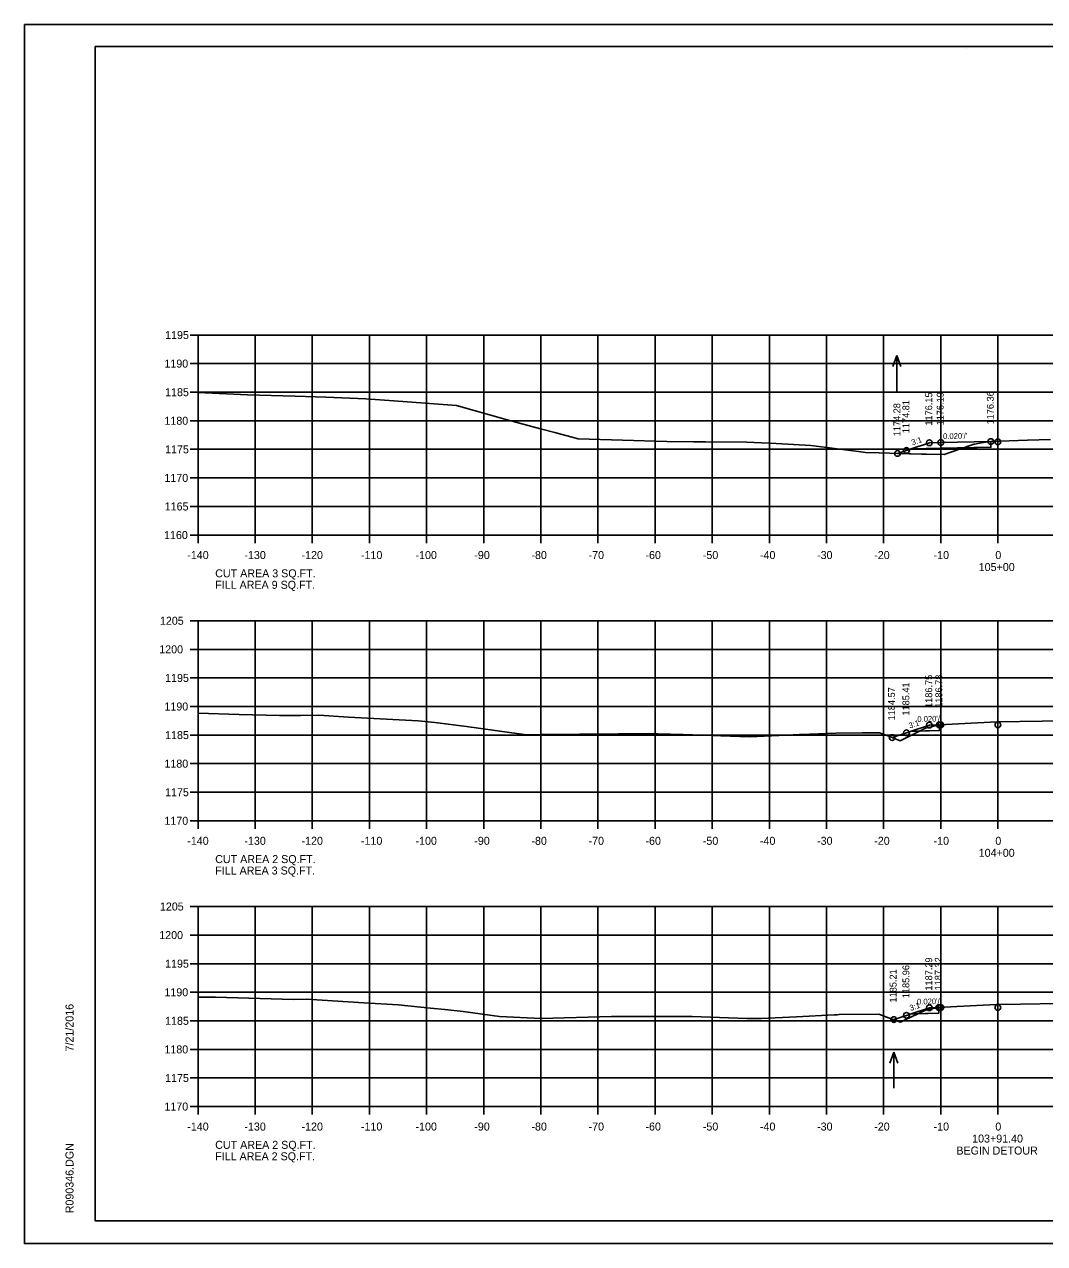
# Model space of a CAD drawing. Extents: x 1368971 to 1374497, y 378717 to 381839.
# Drawn here: x 1372238.5 to 1372417.1, y 380690 to 380903.3 of the extents above; entities that cross this region are included whole.
import ezdxf

# ---------------------------------------------------------------- set-up
doc = ezdxf.new("R2010")
doc.units = 0
for name, color, linetype in [('R_Alt Surface', 7, 'Continuous'), ('R_Axis', 7, 'Continuous'), ('R_Axis Annot', 7, 'Continuous'), ('R_Border', 7, 'Continuous'), ('R_Contours', 7, 'Continuous'), ('R_Exist Surface', 7, 'Continuous'), ('R_Fin Surface', 7, 'Continuous'), ('R_Grid', 7, 'Continuous'), ('R_No Plot', 7, 'Continuous'), ('R_Water Annot', 7, 'Continuous'), ('R_Xsect Elev', 7, 'Continuous'), ('R_Xsect Slope', 7, 'Continuous')]:
    doc.layers.add(name, color=color, linetype=linetype)

msp = doc.modelspace()

# ---------------------------------------------------------------- linework, layer by layer
at = {"layer": 'R_Alt Surface'}
for points in [[(1372407.68, 380830.34), (1372407.68, 380829.34), (1372398.91, 380829.17), (1372393.72, 380829.06)], [(1372398.66, 380780.76), (1372398.66, 380779.76), (1372393.72, 380779.66)], [(1372398.57, 380731.3), (1372398.57, 380730.3), (1372393.72, 380730.21)]]:
    msp.add_lwpolyline(points, dxfattribs=at)
at = {"layer": 'R_Axis'}
for p, q in [((1372267.51, 380848.98), (1372268.91, 380848.98)), ((1372268.91, 380813.98), (1372268.91, 380848.98)), ((1372267.51, 380843.98), (1372268.91, 380843.98)), ((1372267.51, 380838.98), (1372268.91, 380838.98)), ((1372267.51, 380833.98), (1372268.91, 380833.98)), ((1372267.51, 380828.98), (1372268.91, 380828.98)), ((1372267.51, 380823.98), (1372268.91, 380823.98)), ((1372267.51, 380818.98), (1372268.91, 380818.98)), ((1372267.51, 380813.98), (1372268.91, 380813.98)), ((1372268.91, 380813.98), (1372548.91, 380813.98)), ((1372268.91, 380812.58), (1372268.91, 380813.98)), ((1372278.91, 380812.58), (1372278.91, 380813.98)), ((1372288.91, 380812.58), (1372288.91, 380813.98)), ((1372298.91, 380812.58), (1372298.91, 380813.98)), ((1372308.91, 380812.58), (1372308.91, 380813.98)), ((1372318.91, 380812.58), (1372318.91, 380813.98)), ((1372328.91, 380812.58), (1372328.91, 380813.98)), ((1372338.91, 380812.58), (1372338.91, 380813.98)), ((1372348.91, 380812.58), (1372348.91, 380813.98)), ((1372358.91, 380812.58), (1372358.91, 380813.98)), ((1372368.91, 380812.58), (1372368.91, 380813.98)), ((1372378.91, 380812.58), (1372378.91, 380813.98)), ((1372388.91, 380812.58), (1372388.91, 380813.98)), ((1372398.91, 380812.58), (1372398.91, 380813.98)), ((1372408.91, 380812.58), (1372408.91, 380813.98)), ((1372267.51, 380798.98), (1372268.91, 380798.98)), ((1372268.91, 380763.98), (1372268.91, 380798.98)), ((1372267.51, 380793.98), (1372268.91, 380793.98)), ((1372267.51, 380788.98), (1372268.91, 380788.98)), ((1372267.51, 380783.98), (1372268.91, 380783.98)), ((1372267.51, 380778.98), (1372268.91, 380778.98)), ((1372267.51, 380773.98), (1372268.91, 380773.98)), ((1372267.51, 380768.98), (1372268.91, 380768.98)), ((1372267.51, 380763.98), (1372268.91, 380763.98)), ((1372268.91, 380763.98), (1372548.91, 380763.98)), ((1372268.91, 380762.58), (1372268.91, 380763.98)), ((1372278.91, 380762.58), (1372278.91, 380763.98)), ((1372288.91, 380762.58), (1372288.91, 380763.98)), ((1372298.91, 380762.58), (1372298.91, 380763.98)), ((1372308.91, 380762.58), (1372308.91, 380763.98)), ((1372318.91, 380762.58), (1372318.91, 380763.98)), ((1372328.91, 380762.58), (1372328.91, 380763.98)), ((1372338.91, 380762.58), (1372338.91, 380763.98)), ((1372348.91, 380762.58), (1372348.91, 380763.98)), ((1372358.91, 380762.58), (1372358.91, 380763.98)), ((1372368.91, 380762.58), (1372368.91, 380763.98)), ((1372378.91, 380762.58), (1372378.91, 380763.98)), ((1372388.91, 380762.58), (1372388.91, 380763.98)), ((1372398.91, 380762.58), (1372398.91, 380763.98)), ((1372408.91, 380762.58), (1372408.91, 380763.98)), ((1372267.51, 380748.98), (1372268.91, 380748.98)), ((1372268.91, 380713.98), (1372268.91, 380748.98)), ((1372267.51, 380743.98), (1372268.91, 380743.98)), ((1372267.51, 380738.98), (1372268.91, 380738.98)), ((1372267.51, 380733.98), (1372268.91, 380733.98)), ((1372267.51, 380728.98), (1372268.91, 380728.98)), ((1372267.51, 380723.98), (1372268.91, 380723.98)), ((1372267.51, 380718.98), (1372268.91, 380718.98)), ((1372267.51, 380713.98), (1372268.91, 380713.98)), ((1372268.91, 380713.98), (1372548.91, 380713.98)), ((1372268.91, 380712.58), (1372268.91, 380713.98)), ((1372278.91, 380712.58), (1372278.91, 380713.98)), ((1372288.91, 380712.58), (1372288.91, 380713.98)), ((1372298.91, 380712.58), (1372298.91, 380713.98)), ((1372308.91, 380712.58), (1372308.91, 380713.98)), ((1372318.91, 380712.58), (1372318.91, 380713.98)), ((1372328.91, 380712.58), (1372328.91, 380713.98)), ((1372338.91, 380712.58), (1372338.91, 380713.98)), ((1372348.91, 380712.58), (1372348.91, 380713.98)), ((1372358.91, 380712.58), (1372358.91, 380713.98)), ((1372368.91, 380712.58), (1372368.91, 380713.98)), ((1372378.91, 380712.58), (1372378.91, 380713.98)), ((1372388.91, 380712.58), (1372388.91, 380713.98)), ((1372398.91, 380712.58), (1372398.91, 380713.98)), ((1372408.91, 380712.58), (1372408.91, 380713.98))]:
    msp.add_line(p, q, dxfattribs=at)
at = {"layer": 'R_Border'}
for p, q in [((1372250.91, 380899.44), (1372567.09, 380899.44)), ((1372250.91, 380693.98), (1372250.91, 380899.44)), ((1372403.43, 380899.18), (1372403.43, 380899.18)), ((1372403.43, 380899.18), (1372403.43, 380899.18)), ((1372250.91, 380693.98), (1372250.91, 380693.98)), ((1372567.09, 380693.98), (1372250.91, 380693.98))]:
    msp.add_line(p, q, dxfattribs=at)
at = {"layer": 'R_Contours'}
for points in [[(1372391.33, 380828.26), (1372395.51, 380828.16), (1372396.42, 380828.12), (1372399.49, 380828.06), (1372402, 380828.96), (1372402.87, 380829.25), (1372398.91, 380829.17), (1372393.72, 380829.06), (1372392.91, 380828.79)], [(1372402.87, 380829.25), (1372404.77, 380829.87), (1372406.37, 380830.15), (1372407.68, 380830.34), (1372407.68, 380829.34)], [(1372395.23, 380779.69), (1372396.23, 380780.17), (1372397.02, 380780.35), (1372398.66, 380780.76), (1372398.66, 380779.76)], [(1372390.39, 380778.55), (1372391.8, 380777.99), (1372395.17, 380779.67), (1372395.23, 380779.69), (1372393.72, 380779.66), (1372392.91, 380779.39)], [(1372394.92, 380730.23), (1372396.11, 380730.8), (1372397.61, 380731.13), (1372398.57, 380731.3), (1372398.57, 380730.3)], [(1372390.67, 380729.19), (1372391.85, 380728.76), (1372392.69, 380729.15), (1372394.92, 380730.23), (1372393.72, 380730.21), (1372392.91, 380729.94)]]:
    msp.add_lwpolyline(points, close=True, dxfattribs=at)
at = {"layer": 'R_Exist Surface'}
for points in [[(1372268.91, 380838.94), (1372277.57, 380838.53), (1372285.93, 380838.26), (1372291.29, 380838.13), (1372298.29, 380837.83), (1372303.19, 380837.45), (1372314.16, 380836.66), (1372322.99, 380834.15), (1372328.85, 380832.55), (1372331.35, 380831.93), (1372335.44, 380830.84), (1372350.98, 380830.33), (1372355.63, 380830.27), (1372357.71, 380830.28), (1372364.97, 380830.22), (1372370.07, 380829.99), (1372376.18, 380829.62), (1372384.51, 380828.59), (1372385.73, 380828.42), (1372388.15, 380828.35), (1372395.51, 380828.16), (1372396.42, 380828.12), (1372399.49, 380828.06), (1372402, 380828.96), (1372404.77, 380829.87), (1372406.37, 380830.15), (1372407.68, 380830.34), (1372414.1, 380830.59), (1372418.1, 380830.72)], [(1372268.91, 380782.81), (1372276.11, 380782.6), (1372283.18, 380782.38), (1372286.83, 380782.39), (1372290.04, 380782.44), (1372295.23, 380782.09), (1372307.43, 380781.5), (1372310.37, 380781.19), (1372315.87, 380780.5), (1372323.43, 380779.44), (1372325.96, 380779.08), (1372327.07, 380779.02), (1372328.92, 380779.08), (1372342.51, 380779.17), (1372349.38, 380779.18), (1372353.8, 380779.1), (1372363.72, 380778.72), (1372365.48, 380778.66), (1372373.08, 380779.03), (1372374.16, 380779.08), (1372374.44, 380779.09), (1372380.54, 380779.31), (1372385.13, 380779.35), (1372388.17, 380779.39), (1372389.98, 380778.71), (1372391.8, 380777.99), (1372395.17, 380779.67), (1372396.23, 380780.17), (1372397.02, 380780.35), (1372398.66, 380780.76), (1372405.35, 380781.12), (1372408.81, 380781.3), (1372416.67, 380781.41), (1372419.84, 380781.45)], [(1372268.91, 380733.14), (1372271.97, 380733.1), (1372281.73, 380732.82), (1372285.53, 380732.73), (1372287.87, 380732.78), (1372297.92, 380732.1), (1372303.92, 380731.8), (1372309.57, 380731.22), (1372312.09, 380730.96), (1372315.32, 380730.64), (1372321.7, 380729.75), (1372328.96, 380729.38), (1372341.29, 380729.76), (1372341.37, 380729.76), (1372341.52, 380729.76), (1372352.86, 380729.73), (1372355.4, 380729.74), (1372364.97, 380729.39), (1372367.5, 380729.41), (1372373.66, 380729.67), (1372380.23, 380730.03), (1372380.75, 380730.05), (1372381.14, 380730.06), (1372388.08, 380730.15), (1372390.23, 380729.35), (1372391.85, 380728.76), (1372392.69, 380729.15), (1372396.11, 380730.8), (1372397.61, 380731.13), (1372398.57, 380731.3), (1372401.75, 380731.48), (1372408.68, 380731.86), (1372412.88, 380731.92), (1372419.7, 380732.02)]]:
    msp.add_lwpolyline(points, dxfattribs=at)
at = {"layer": 'R_Fin Surface'}
for points in [[(1372391.33, 380828.26), (1372392.91, 380828.79), (1372393.72, 380829.06), (1372396.91, 380830.13), (1372398.91, 380830.17), (1372407.68, 380830.34)], [(1372390.39, 380778.55), (1372392.91, 380779.39), (1372393.72, 380779.66), (1372396.91, 380780.73), (1372398.66, 380780.76), (1372398.91, 380780.77)], [(1372390.67, 380729.19), (1372392.91, 380729.94), (1372393.72, 380730.21), (1372396.91, 380731.27), (1372398.57, 380731.3), (1372398.91, 380731.31)]]:
    msp.add_lwpolyline(points, dxfattribs=at)
at = {"layer": 'R_Grid'}
for p, q in [((1372268.91, 380848.98), (1372548.91, 380848.98)), ((1372268.91, 380813.98), (1372268.91, 380848.98)), ((1372278.91, 380813.98), (1372278.91, 380848.98)), ((1372288.91, 380813.98), (1372288.91, 380848.98)), ((1372298.91, 380813.98), (1372298.91, 380848.98)), ((1372308.91, 380813.98), (1372308.91, 380848.98)), ((1372318.91, 380813.98), (1372318.91, 380848.98)), ((1372328.91, 380813.98), (1372328.91, 380848.98)), ((1372338.91, 380813.98), (1372338.91, 380848.98)), ((1372348.91, 380813.98), (1372348.91, 380848.98)), ((1372358.91, 380813.98), (1372358.91, 380848.98)), ((1372368.91, 380813.98), (1372368.91, 380848.98)), ((1372378.91, 380813.98), (1372378.91, 380848.98)), ((1372388.91, 380813.98), (1372388.91, 380848.98)), ((1372398.91, 380813.98), (1372398.91, 380848.98)), ((1372408.91, 380813.98), (1372408.91, 380848.98)), ((1372268.91, 380843.98), (1372548.91, 380843.98)), ((1372268.91, 380838.98), (1372548.91, 380838.98)), ((1372268.91, 380833.98), (1372548.91, 380833.98)), ((1372268.91, 380828.98), (1372548.91, 380828.98)), ((1372268.91, 380823.98), (1372548.91, 380823.98)), ((1372268.91, 380818.98), (1372548.91, 380818.98)), ((1372268.91, 380813.98), (1372548.91, 380813.98)), ((1372268.91, 380798.98), (1372548.91, 380798.98)), ((1372268.91, 380763.98), (1372268.91, 380798.98)), ((1372278.91, 380763.98), (1372278.91, 380798.98)), ((1372288.91, 380763.98), (1372288.91, 380798.98)), ((1372298.91, 380763.98), (1372298.91, 380798.98)), ((1372308.91, 380763.98), (1372308.91, 380798.98)), ((1372318.91, 380763.98), (1372318.91, 380798.98)), ((1372328.91, 380763.98), (1372328.91, 380798.98)), ((1372338.91, 380763.98), (1372338.91, 380798.98)), ((1372348.91, 380763.98), (1372348.91, 380798.98)), ((1372358.91, 380763.98), (1372358.91, 380798.98)), ((1372368.91, 380763.98), (1372368.91, 380798.98)), ((1372378.91, 380763.98), (1372378.91, 380798.98)), ((1372388.91, 380763.98), (1372388.91, 380798.98)), ((1372398.91, 380763.98), (1372398.91, 380798.98)), ((1372408.91, 380763.98), (1372408.91, 380798.98)), ((1372268.91, 380793.98), (1372548.91, 380793.98)), ((1372268.91, 380788.98), (1372548.91, 380788.98)), ((1372268.91, 380783.98), (1372548.91, 380783.98)), ((1372268.91, 380778.98), (1372548.91, 380778.98)), ((1372268.91, 380773.98), (1372548.91, 380773.98)), ((1372268.91, 380768.98), (1372548.91, 380768.98)), ((1372268.91, 380763.98), (1372548.91, 380763.98)), ((1372268.91, 380748.98), (1372548.91, 380748.98)), ((1372268.91, 380713.98), (1372268.91, 380748.98)), ((1372278.91, 380713.98), (1372278.91, 380748.98)), ((1372288.91, 380713.98), (1372288.91, 380748.98)), ((1372298.91, 380713.98), (1372298.91, 380748.98)), ((1372308.91, 380713.98), (1372308.91, 380748.98)), ((1372318.91, 380713.98), (1372318.91, 380748.98)), ((1372328.91, 380713.98), (1372328.91, 380748.98)), ((1372338.91, 380713.98), (1372338.91, 380748.98)), ((1372348.91, 380713.98), (1372348.91, 380748.98)), ((1372358.91, 380713.98), (1372358.91, 380748.98)), ((1372368.91, 380713.98), (1372368.91, 380748.98)), ((1372378.91, 380713.98), (1372378.91, 380748.98)), ((1372388.91, 380713.98), (1372388.91, 380748.98)), ((1372398.91, 380713.98), (1372398.91, 380748.98)), ((1372408.91, 380713.98), (1372408.91, 380748.98)), ((1372268.91, 380743.98), (1372548.91, 380743.98)), ((1372268.91, 380738.98), (1372548.91, 380738.98)), ((1372268.91, 380733.98), (1372548.91, 380733.98)), ((1372268.91, 380728.98), (1372548.91, 380728.98)), ((1372268.91, 380723.98), (1372548.91, 380723.98)), ((1372268.91, 380718.98), (1372548.91, 380718.98)), ((1372268.91, 380713.98), (1372548.91, 380713.98))]:
    msp.add_line(p, q, dxfattribs=at)
at = {"layer": 'R_No Plot'}
for p, q in [((1372238.51, 380903.33), (1372571.85, 380903.33)), ((1372238.51, 380690), (1372571.85, 380690))]:
    msp.add_line(p, q, dxfattribs=at)
for points in [[(1372238.51, 380903.33), (1372571.85, 380903.33), (1372571.85, 380690), (1372238.51, 380690)], [(1372484.83, 380899.44), (1372484.83, 380889.56), (1372520.57, 380889.56), (1372520.57, 380886.64), (1372543.77, 380886.64), (1372543.77, 380863.43), (1372567.09, 380863.43), (1372567.09, 380693.98), (1372250.91, 380693.98), (1372250.91, 380899.44)]]:
    msp.add_lwpolyline(points, close=True, dxfattribs=at)
for centre in [(1372392.91, 380828.79), (1372396.91, 380830.13), (1372398.91, 380830.17), (1372407.68, 380830.34), (1372408.91, 380830.29), (1372391.33, 380828.26), (1372392.91, 380779.39), (1372396.91, 380780.73), (1372398.66, 380780.76), (1372398.91, 380780.77), (1372408.91, 380780.77), (1372390.39, 380778.55), (1372396.91, 380731.27), (1372398.57, 380731.3), (1372398.91, 380731.31), (1372408.91, 380731.32), (1372390.67, 380729.19), (1372392.91, 380729.94)]:
    msp.add_circle(centre, 0.5, dxfattribs=at)
at = {"layer": 'R_Water Annot'}
for p, q in [((1372391.2, 380845.41), (1372390.5, 380843.48)), ((1372391.2, 380839.12), (1372391.2, 380845.41)), ((1372391.2, 380845.41), (1372391.9, 380843.48)), ((1372390.71, 380723.47), (1372390.01, 380721.55)), ((1372390.71, 380717.19), (1372390.71, 380723.47)), ((1372390.71, 380723.47), (1372391.41, 380721.55))]:
    msp.add_line(p, q, dxfattribs=at)

# ---------------------------------------------------------------- texts
at = {"layer": 'R_Axis'}
for p in [(1372268.91, 380813.98), (1372268.91, 380763.98), (1372268.91, 380713.98)]:
    msp.add_text('-', height=0.0001, dxfattribs=at).set_placement(p)
at = {"layer": 'R_Axis Annot'}
for s, p in [('1195', (1372263.14, 380848.28)), ('1190', (1372263.02, 380843.28)), ('1185', (1372263.14, 380838.28)), ('1180', (1372263.02, 380833.28)), ('1175', (1372263.14, 380828.28)), ('1170', (1372263.02, 380823.28)), ('1165', (1372263.07, 380818.28)), ('1160', (1372262.95, 380813.28)), ('-140', (1372267.02, 380809.78)), ('-130', (1372277.02, 380809.78)), ('-120', (1372287.02, 380809.78)), ('-110', (1372297.42, 380809.78)), ('-100', (1372306.97, 380809.78)), ('-90', (1372317.26, 380809.78)), ('-80', (1372327.26, 380809.78)), ('-70', (1372337.26, 380809.78)), ('-60', (1372347.22, 380809.78)), ('-50', (1372357.26, 380809.78)), ('-40', (1372367.26, 380809.78)), ('-30', (1372377.26, 380809.78)), ('-20', (1372387.26, 380809.78)), ('-10', (1372397.65, 380809.78)), ('0', (1372408.46, 380809.78)), ('CUT AREA 3 SQ.FT.', (1372271.91, 380806.58)), ('105+00', (1372405.55, 380807.68)), ('FILL AREA 9 SQ.FT.', (1372271.91, 380804.58)), ('1205', (1372262.23, 380798.28)), ('1200', (1372262.11, 380793.28)), ('1195', (1372263.14, 380788.28)), ('1190', (1372263.02, 380783.28)), ('1185', (1372263.14, 380778.28)), ('1180', (1372263.02, 380773.28)), ('1175', (1372263.14, 380768.28)), ('1170', (1372263.02, 380763.28)), ('-140', (1372267.02, 380759.78)), ('-130', (1372277.02, 380759.78)), ('-120', (1372287.02, 380759.78)), ('-110', (1372297.42, 380759.78)), ('-100', (1372306.97, 380759.78)), ('-90', (1372317.26, 380759.78)), ('-80', (1372327.26, 380759.78)), ('-70', (1372337.26, 380759.78)), ('-60', (1372347.22, 380759.78)), ('-50', (1372357.26, 380759.78)), ('-40', (1372367.26, 380759.78)), ('-30', (1372377.26, 380759.78)), ('-20', (1372387.26, 380759.78)), ('-10', (1372397.65, 380759.78)), ('0', (1372408.46, 380759.78)), ('104+00', (1372405.55, 380757.68)), ('CUT AREA 2 SQ.FT.', (1372271.91, 380756.58)), ('FILL AREA 3 SQ.FT.', (1372271.91, 380754.58)), ('1205', (1372262.23, 380748.28)), ('1200', (1372262.11, 380743.28)), ('1195', (1372263.14, 380738.28)), ('1190', (1372263.02, 380733.28)), ('1185', (1372263.14, 380728.28)), ('1180', (1372263.02, 380723.28)), ('1175', (1372263.14, 380718.28)), ('1170', (1372263.02, 380713.28)), ('-140', (1372267.02, 380709.78)), ('-130', (1372277.02, 380709.78)), ('-120', (1372287.02, 380709.78)), ('-110', (1372297.42, 380709.78)), ('-100', (1372306.97, 380709.78)), ('-90', (1372317.26, 380709.78)), ('-80', (1372327.26, 380709.78)), ('-70', (1372337.26, 380709.78)), ('-60', (1372347.22, 380709.78)), ('-50', (1372357.26, 380709.78)), ('-40', (1372367.26, 380709.78)), ('-30', (1372377.26, 380709.78)), ('-20', (1372387.26, 380709.78)), ('-10', (1372397.65, 380709.78)), ('0', (1372408.46, 380709.78)), ('CUT AREA 2 SQ.FT.', (1372271.91, 380706.58)), ('103+91.40', (1372404.4, 380707.68)), ('FILL AREA 2 SQ.FT.', (1372271.91, 380704.58)), ('BEGIN DETOUR', (1372401.64, 380705.58))]:
    msp.add_text(s, height=1.4, dxfattribs=at).set_placement(p)
at = {"layer": 'R_Border'}
for s, p in [('7/21/2016', (1372247.11, 380723.62)), ('R090346.DGN', (1372247.11, 380695.3))]:
    msp.add_text(s, height=1.4, rotation=90, dxfattribs=at).set_placement(p)
at = {"layer": 'R_Xsect Elev'}
for s, p in [('1174.81', (1372393.41, 380831.79)), ('1176.15', (1372397.41, 380833.13)), ('1176.19', (1372399.41, 380833.17)), ('1176.36', (1372408.18, 380833.34)), ('1174.28', (1372391.83, 380831.26)), ('1186.75', (1372397.41, 380783.73)), ('1186.78', (1372399.16, 380783.76)), ('1184.57', (1372390.89, 380781.55)), ('1185.41', (1372393.41, 380782.39)), ('1187.29', (1372397.41, 380734.27)), ('1187.32', (1372399.07, 380734.3)), ('1185.21', (1372391.17, 380732.19)), ('1185.96', (1372393.41, 380732.94))]:
    msp.add_text(s, height=1.2, rotation=90, dxfattribs=at).set_placement(p)
at = {"layer": 'R_Xsect Slope'}
for s, rotation, p in [('3:1', 18.4337, (1372393.96, 380829.67)), ("0.020'/'", 1.1458, (1372399.32, 380830.77)), ("0.020'/'", 1.1458, (1372394.81, 380781.28)), ('3:1', 18.4339, (1372393.49, 380780.11)), ("0.020'/'", 1.1458, (1372394.76, 380731.83)), ('3:1', 18.4338, (1372393.64, 380730.7))]:
    msp.add_text(s, height=1, rotation=rotation, dxfattribs=at).set_placement(p)

doc.saveas('drawing.dxf')
